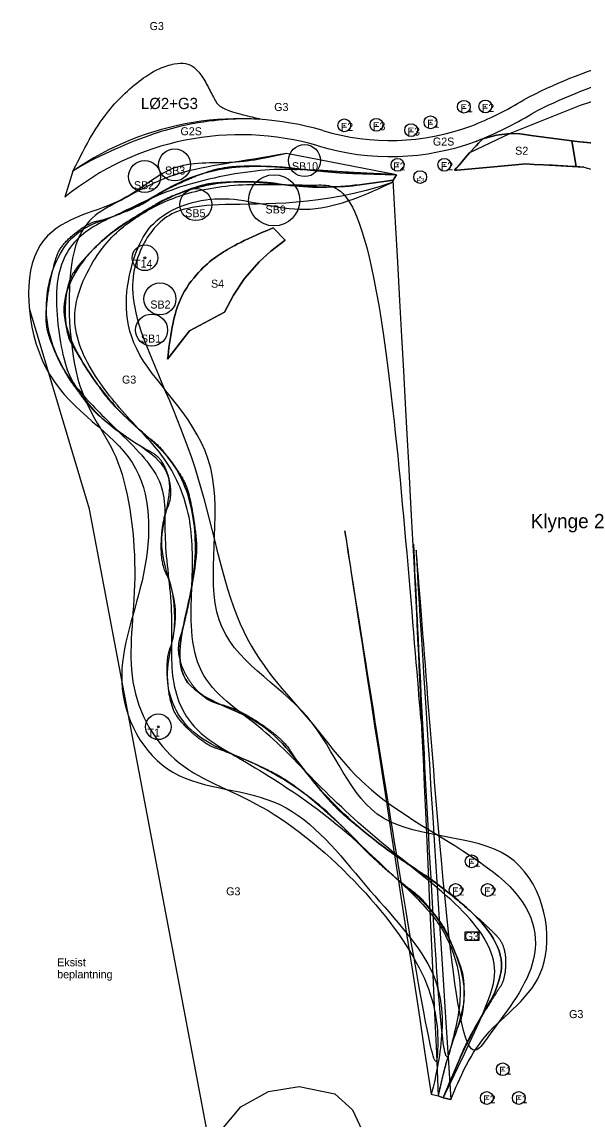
# Model space of a CAD drawing. Extents: x 0 to 512122, y 0 to 6212554.
# Drawn here: x 511416.7 to 511504.4, y 6211506.3 to 6211677.6 of the extents above; entities that cross this region are included whole.
import ezdxf

# ---------------------------------------------------------------- set-up
doc = ezdxf.new("R2010")
doc.units = 0
for name, color, linetype in [('_color plan_G3', 7, 'Continuous'), ('_LØ2', 7, 'Continuous'), ('_ny fruit trees', 7, 'Continuous'), ('_ny grøft', 7, 'Continuous'), ('_Paths', 7, 'Continuous'), ('_S1_rabarber', 7, 'Continuous'), ('_S2_skovjorbær', 7, 'Continuous'), ('_S4_Løvstikke', 7, 'Continuous'), ('L40 jord udlagt muld og grøft', 7, 'Continuous'), ('MatrikelnummerMaster', 7, 'Continuous'), ('Skel', 7, 'Continuous'), ('TV_U_AFM_Symbl_Gul', 7, 'Continuous'), ('TV_U_LYS_Ledn-ror', 7, 'Continuous'), ('TV_U_LYS_Mastenummer', 7, 'Continuous'), ('TV_U_LYS_Nyx330-Trafiksti-x2', 7, 'Continuous')]:
    doc.layers.add(name, color=color, linetype=linetype)

# ---------------------------------------------------------------- blocks, each defined once
blk = doc.blocks.new('SOLITAIRE TREES')
at = {"layer": 'Skel'}
for radius in [2, 0.141]:
    blk.add_circle((0, 0), radius, dxfattribs=at)

msp = doc.modelspace()

# ---------------------------------------------------------------- linework, layer by layer
at = {"layer": '_color plan_G3'}
for p, q in [((511427.31, 6211601.52), (511417.91, 6211632.84)), ((511446.41, 6211500.58), (511427.31, 6211601.52))]:
    msp.add_line(p, q, dxfattribs=at)
at = {"layer": '_LØ2'}
msp.add_open_spline([(511424.7, 6211654.29), (511428.07, 6211656.43), (511437.64, 6211660.56), (511445.41, 6211662.15), (511451.17, 6211662.51), (511454.35, 6211662.34), (511453.5, 6211662.56), (511449.68, 6211663.42), (511447.75, 6211664.26), (511447.04, 6211665.01), (511446.02, 6211667.09), (511444.88, 6211669.21), (511443.53, 6211670.64), (511442.41, 6211671.16), (511440.65, 6211671.16), (511438.15, 6211670.34), (511435.89, 6211669.05), (511432.77, 6211666.48), (511430.26, 6211663.8), (511427.67, 6211660.13), (511424.7, 6211654.29), (511424.7, 6211654.29), (511424.7, 6211654.29)], degree=3, dxfattribs=at)
at = {"layer": '_ny fruit trees'}
for centre, radius in [((511485.78, 6211664.33), 1), ((511489.13, 6211664.38), 1), ((511485.78, 6211664.33), 0.0426), ((511489.13, 6211664.38), 0.0426), ((511467.09, 6211661.42), 1), ((511472.12, 6211661.51), 1), ((511480.57, 6211661.9), 1), ((511480.57, 6211661.9), 0.0426), ((511467.09, 6211661.42), 0.0426), ((511472.12, 6211661.51), 0.0426), ((511477.54, 6211660.68), 1), ((511477.54, 6211660.68), 0.0426), ((511475.42, 6211655.26), 1), ((511475.42, 6211655.26), 0.0426), ((511482.72, 6211655.27), 1), ((511482.72, 6211655.27), 0.0426), ((511478.95, 6211653.35), 1), ((511478.95, 6211653.35), 0.0426), ((511486.99, 6211546.53), 1), ((511486.99, 6211546.53), 0.0426), ((511484.49, 6211542.06), 1), ((511484.49, 6211542.06), 0.0426), ((511489.49, 6211542.06), 1), ((511489.49, 6211542.06), 0.0426), ((511491.86, 6211514.07), 1), ((511491.86, 6211514.07), 0.0426), ((511489.36, 6211509.59), 1), ((511489.36, 6211509.59), 0.0426), ((511494.36, 6211509.59), 1), ((511494.36, 6211509.59), 0.0426)]:
    msp.add_circle(centre, radius, dxfattribs=at)
at = {"layer": '_ny grøft'}
for p, q in [((511474.76, 6211652.85), (511475.27, 6211653.72)), ((511481.79, 6211509.92), (511482.56, 6211509.63))]:
    msp.add_line(p, q, dxfattribs=at)
for points in [[(511475.27, 6211653.72), (511461.62, 6211654.47), (511455.63, 6211655.03), (511441.12, 6211652.28), (511432.39, 6211647.75), (511425.04, 6211644.58), (511421.2, 6211637.22), (511423.26, 6211623.35), (511425.38, 6211620.08), (511431.34, 6211614.04), (511439.77, 6211606.02), (511438.57, 6211597.36), (511440.58, 6211585.48), (511439.53, 6211574.34), (511443.41, 6211566.53), (511450.84, 6211562.71), (511464.22, 6211554.28), (511474.17, 6211544.78), (511480.99, 6211538.55), (511484.19, 6211532.91), (511485.83, 6211525.83), (511483.67, 6211517.14), (511481.79, 6211509.92), (511475.27, 6211653.72), (511481.79, 6211509.92)], [(511482.56, 6211509.63), (511489.4, 6211523.73), (511492.28, 6211529.95), (511486.36, 6211539.12), (511472.41, 6211549.47), (511461.9, 6211559.42), (511454.45, 6211567.71), (511442.74, 6211574.97), (511443.32, 6211589.8), (511443.59, 6211599.75), (511439.99, 6211609.06), (511433.64, 6211615.22), (511427.09, 6211623.08), (511423.49, 6211632.32), (511429.32, 6211643.41), (511435.09, 6211647.54), (511441.15, 6211650.76), (511450.85, 6211652.59), (511462.71, 6211651.81), (511474.76, 6211652.85), (511482.56, 6211509.63), (511474.76, 6211652.85)]]:
    msp.add_open_spline(points, degree=3, dxfattribs=at)
at = {"layer": '_Paths'}
msp.add_line((511424.7, 6211654.29), (511423.42, 6211650.2), dxfattribs=at)
msp.add_lwpolyline([(511487.79, 6211658.98), (511487.77, 6211658.97), (511487.75, 6211658.97)], dxfattribs=at)
for centre, radius, start, end in [((511530.83, 6211597.57), 76.66, 105.9873, 117.7388), ((511530.83, 6211597.57), 74.16, 105.9889, 117.6767), ((511468, 6211709.71), 51.95, 291.3096, 301.5015), ((511450.83, 6211616.67), 45.8, 73.6335, 124.7812), ((511468, 6211709.71), 54.45, 291.3096, 301.4133), ((511474.27, 6211695.48), 36.42, 253.1824, 290.2638), ((511450.83, 6211616.67), 43.3, 73.6461, 129.2584), ((511474.27, 6211695.48), 38.92, 253.1974, 290.2638)]:
    msp.add_arc(centre, radius, start, end, dxfattribs=at)
at = {"layer": '_S1_rabarber'}
for points in [[(511503.34, 6211654.98), (511502.63, 6211659), (511503.91, 6211658.84), (511512.53, 6211658.04)], [(511513.47, 6211657.95), (511503.91, 6211658.84), (511502.63, 6211659), (511503.34, 6211654.98), (511504.51, 6211654.89)], [(511504.51, 6211654.89), (511503.34, 6211654.98)]]:
    msp.add_lwpolyline(points, dxfattribs=at)
at = {"layer": '_S2_skovjorbær'}
msp.add_lwpolyline([(511503.34, 6211654.98), (511502.63, 6211659), (511496.67, 6211659.79), (511495.32, 6211659.98), (511494.51, 6211660.09), (511493.04, 6211660.13), (511490.89, 6211659.92), (511488.72, 6211659.33), (511488.05, 6211658.62), (511487.71, 6211658.25), (511486.68, 6211657.15), (511485.97, 6211656.37), (511485.5, 6211655.78), (511485.29, 6211655.54), (511485.04, 6211655.22), (511484.65, 6211654.8), (511484.32, 6211654.41), (511484.32, 6211654.41), (511484.32, 6211654.41), (511484.74, 6211654.44), (511489.91, 6211654.92), (511492.7, 6211655.16), (511495.49, 6211655.44), (511496.78, 6211655.34), (511499.65, 6211655.23), (511502.01, 6211655.06), (511503.34, 6211654.98)], dxfattribs=at)
msp.add_lwpolyline([(511502.01, 6211655.06), (511499.65, 6211655.23), (511496.78, 6211655.34), (511495.49, 6211655.44), (511492.7, 6211655.16), (511489.91, 6211654.92), (511484.74, 6211654.44), (511484.32, 6211654.41), (511484.65, 6211654.8), (511485.04, 6211655.22), (511485.29, 6211655.54), (511485.5, 6211655.78), (511485.97, 6211656.37), (511486.68, 6211657.15), (511487.71, 6211658.25), (511488.05, 6211658.62), (511488.72, 6211659.33), (511490.89, 6211659.92), (511493.04, 6211660.13), (511494.51, 6211660.09), (511496.67, 6211659.79), (511502.63, 6211659), (511503.34, 6211654.98)], close=True, dxfattribs=at)
at = {"layer": '_S4_Løvstikke'}
for points in [[(511439.49, 6211624.95), (511442.9, 6211629.35), (511448.4, 6211632.28), (511449.8, 6211634.9), (511451.53, 6211637.52), (511453.79, 6211640.12), (511455.62, 6211641.78), (511457.84, 6211643.49), (511455.99, 6211645.42)], [(511455.99, 6211645.42), (511457.84, 6211643.49), (511455.62, 6211641.78), (511453.79, 6211640.12), (511451.53, 6211637.52), (511449.8, 6211634.9), (511448.4, 6211632.28), (511442.9, 6211629.35), (511439.49, 6211624.95)]]:
    msp.add_lwpolyline(points, dxfattribs=at)
for points in [[(511455.99, 6211645.42), (511450.89, 6211643.32), (511447.17, 6211641.07), (511444.84, 6211639.2), (511441.51, 6211635.17), (511440.06, 6211629.91), (511439.66, 6211626.47), (511439.49, 6211624.95)], [(511439.49, 6211624.95), (511439.66, 6211626.47), (511440.06, 6211629.91), (511441.51, 6211635.17), (511444.84, 6211639.2), (511447.17, 6211641.07), (511450.89, 6211643.32), (511455.99, 6211645.42)]]:
    msp.add_open_spline(points, degree=3, dxfattribs=at)
at = {"layer": 'L40 jord udlagt muld og grøft'}
for p, q in [((511475.27, 6211653.72), (511458.09, 6211657.05)), ((511475.27, 6211653.72), (511458.09, 6211657.05)), ((511475.27, 6211653.72), (511474.76, 6211652.85)), ((511474.76, 6211652.85), (511474.56, 6211652.51)), ((511474.56, 6211652.51), (511474.76, 6211652.85)), ((511480.69, 6211510.17), (511481.79, 6211509.92)), ((511480.69, 6211510.17), (511481.79, 6211509.92)), ((511482.56, 6211509.63), (511481.79, 6211509.92)), ((511483.74, 6211509.33), (511482.56, 6211509.63)), ((511482.56, 6211509.63), (511483.74, 6211509.33))]:
    msp.add_line(p, q, dxfattribs=at)
msp.add_lwpolyline([(511485.92, 6211535.46), (511485.92, 6211534.21), (511488.18, 6211534.21), (511488.18, 6211535.46)], close=True, dxfattribs=at)
for points, degree in [([(511458.09, 6211657.05), (511455.68, 6211656.49), (511449.86, 6211655.14), (511439.81, 6211656.13), (511432.57, 6211648.34), (511415.88, 6211645.78), (511418.42, 6211619.6), (511437.09, 6211610.57), (511436.92, 6211590.82), (511429.65, 6211574.72), (511438.49, 6211557.45), (511458.39, 6211558.11), (511470.26, 6211542.38), (511482.66, 6211529.65), (511482.5, 6211517.37), (511481.15, 6211511.98), (511480.69, 6211510.17)], 3), ([(511458.09, 6211657.05), (511450.76, 6211655.72), (511440.25, 6211654.54), (511431.71, 6211649.18), (511423.32, 6211645.64), (511424.22, 6211618.55), (511432.73, 6211611.07), (511435.28, 6211589.93), (511432.23, 6211574.25), (511440.19, 6211560.26), (511454.86, 6211556.18), (511471.47, 6211541.66), (511481.58, 6211526.77), (511481.91, 6211515.67), (511480.69, 6211510.17), (511458.09, 6211657.05), (511480.69, 6211510.17)], 3), ([(511481.79, 6211509.92), (511482.35, 6211512.33), (511483.58, 6211517.63), (511486.76, 6211525.23), (511484.49, 6211532.79), (511480.87, 6211539.63), (511472.71, 6211545.48), (511464.18, 6211555.25), (511453.41, 6211562.14), (511442.62, 6211565.61), (511437.96, 6211575.2), (511442.41, 6211585.85), (511436.7, 6211596.01), (511442.33, 6211607.71), (511431.47, 6211613.15), (511426.2, 6211618.74), (511421.25, 6211626.12), (511419.76, 6211635.3), (511424.12, 6211645.62), (511433.33, 6211647.42), (511442.15, 6211653.77), (511452.77, 6211655.6), (511464.14, 6211654.06), (511470.71, 6211653.86), (511475.27, 6211653.72)], 3), ([(511481.79, 6211509.92), (511482.35, 6211512.33), (511483.58, 6211517.63), (511486.76, 6211525.23), (511484.49, 6211532.79), (511480.87, 6211539.63), (511472.71, 6211545.48), (511464.18, 6211555.25), (511453.41, 6211562.14), (511442.62, 6211565.61), (511437.96, 6211575.2), (511442.41, 6211585.85), (511436.7, 6211596.01), (511442.33, 6211607.71), (511431.47, 6211613.15), (511426.2, 6211618.74), (511421.25, 6211626.12), (511419.76, 6211635.3), (511424.12, 6211645.62), (511433.33, 6211647.42), (511442.15, 6211653.77), (511452.77, 6211655.6), (511464.14, 6211654.06), (511470.71, 6211653.86), (511475.27, 6211653.72)], 3), ([(511441.12, 6211652.28), (511445.57, 6211654.36), (511450.69, 6211655.24), (511455.63, 6211655.03)], 2), ([(511455.63, 6211655.03), (511457.65, 6211654.94), (511459.63, 6211654.67), (511461.62, 6211654.47)], 2), ([(511461.62, 6211654.47), (511466.15, 6211654), (511470.71, 6211653.86), (511475.27, 6211653.72)], 2), ([(511482.56, 6211509.63), (511484.52, 6211514.31), (511487.33, 6211521.04), (511494.46, 6211531.2), (511484.43, 6211541.62), (511473.09, 6211548.33), (511462.09, 6211558.19), (511455.18, 6211569.44), (511438.69, 6211572.97), (511443.7, 6211588.59), (511444.23, 6211599.66), (511440.98, 6211609.39), (511432.98, 6211615.29), (511426.97, 6211622.66), (511421.35, 6211633.12), (511427.65, 6211642.85), (511434.98, 6211647.51), (511441.89, 6211651.59), (511451.56, 6211653.25), (511462.77, 6211651.15), (511470.74, 6211652.28), (511474.76, 6211652.85)], 3), ([(511474.76, 6211652.85), (511470.74, 6211652.28), (511462.77, 6211651.15), (511451.56, 6211653.25), (511441.89, 6211651.59), (511434.98, 6211647.51), (511427.65, 6211642.85), (511421.35, 6211633.12), (511426.97, 6211622.66), (511432.98, 6211615.29), (511440.98, 6211609.39), (511444.23, 6211599.66), (511443.7, 6211588.59), (511438.69, 6211572.97), (511455.18, 6211569.44), (511462.09, 6211558.19), (511473.09, 6211548.33), (511484.43, 6211541.62), (511494.46, 6211531.2), (511487.33, 6211521.04), (511484.52, 6211514.31), (511482.56, 6211509.63)], 3), ([(511483.74, 6211509.33), (511485.11, 6211512.64), (511488.42, 6211520.65), (511501.36, 6211528.2), (511496.23, 6211551.58), (511469.85, 6211549.2), (511463.78, 6211571.11), (511442.68, 6211581.04), (511450.76, 6211610.16), (511431.68, 6211625.71), (511433.47, 6211640.43), (511437.47, 6211647.98), (511448.92, 6211651.3), (511461.52, 6211646.46), (511470.94, 6211650.83), (511474.56, 6211652.51)], 3), ([(511432.39, 6211647.75), (511435.49, 6211648.98), (511438.16, 6211650.89), (511441.12, 6211652.28)], 2), ([(511474.56, 6211652.51), (511463.59, 6211648.7), (511444.99, 6211649.71), (511438.23, 6211647.27), (511434.17, 6211640.84), (511433.22, 6211631.63), (511444.92, 6211608.82), (511449.42, 6211581.02), (511462.31, 6211568.82), (511470.45, 6211556.04), (511495.94, 6211543.51), (511498.54, 6211530.24), (511488.73, 6211518.74), (511483.74, 6211509.33), (511474.56, 6211652.51), (511483.74, 6211509.33)], 3), ([(511450.85, 6211652.59), (511447.54, 6211652.56), (511444.21, 6211651.99), (511441.15, 6211650.76)], 2), ([(511462.71, 6211651.81), (511458.77, 6211651.9), (511454.83, 6211652.64), (511450.85, 6211652.59)], 2), ([(511474.76, 6211652.85), (511470.74, 6211652.28), (511466.72, 6211651.71), (511462.71, 6211651.81)], 2), ([(511441.15, 6211650.76), (511439.03, 6211649.9), (511437.04, 6211648.73), (511435.09, 6211647.54)], 2), ([(511425.04, 6211644.58), (511427.04, 6211646.19), (511429.86, 6211646.74), (511432.39, 6211647.75)], 2), ([(511435.09, 6211647.54), (511433.08, 6211646.31), (511431.12, 6211645.06), (511429.32, 6211643.41)], 2), ([(511421.2, 6211637.22), (511421.78, 6211640.07), (511422.97, 6211642.9), (511425.04, 6211644.58)], 2), ([(511429.32, 6211643.41), (511426.14, 6211640.51), (511423.47, 6211636.39), (511423.49, 6211632.32)], 2), ([(511423.26, 6211623.35), (511421.03, 6211627.48), (511420.23, 6211632.39), (511421.2, 6211637.22)], 2), ([(511423.49, 6211632.32), (511423.51, 6211629.11), (511425.21, 6211625.94), (511427.09, 6211623.08)], 2), ([(511425.38, 6211620.08), (511424.61, 6211621.12), (511423.88, 6211622.2), (511423.26, 6211623.35)], 2), ([(511427.09, 6211623.08), (511429.03, 6211620.14), (511431.15, 6211617.54), (511433.64, 6211615.22)], 2), ([(511431.34, 6211614.04), (511428.91, 6211615.86), (511427.05, 6211617.84), (511425.38, 6211620.08)], 2), ([(511439.77, 6211606.02), (511439.04, 6211609.36), (511434.66, 6211611.55), (511431.34, 6211614.04)], 2), ([(511433.64, 6211615.22), (511435.79, 6211613.21), (511438.23, 6211611.41), (511439.99, 6211609.06)], 2), ([(511439.99, 6211609.06), (511441.98, 6211606.4), (511443.11, 6211603.02), (511443.59, 6211599.75)], 2), ([(511438.57, 6211597.36), (511438.8, 6211600.36), (511440.31, 6211603.51), (511439.77, 6211606.02)], 2), ([(511443.59, 6211599.75), (511444.08, 6211596.48), (511443.93, 6211593.32), (511443.32, 6211589.8)], 2), ([(511440.58, 6211585.48), (511440.41, 6211589.41), (511438.26, 6211593.23), (511438.57, 6211597.36)], 2), ([(511443.32, 6211589.8), (511442.41, 6211584.56), (511440.48, 6211578.55), (511442.74, 6211574.97)], 2), ([(511439.53, 6211574.34), (511439.17, 6211578.11), (511440.73, 6211581.84), (511440.58, 6211585.48)], 2), ([(511442.74, 6211574.97), (511444.84, 6211571.65), (511450.56, 6211570.43), (511454.45, 6211567.71)], 2), ([(511443.41, 6211566.53), (511441.25, 6211568.45), (511439.81, 6211571.4), (511439.53, 6211574.34)], 2), ([(511454.45, 6211567.71), (511457.6, 6211565.51), (511459.55, 6211562.33), (511461.9, 6211559.42)], 2), ([(511450.84, 6211562.71), (511448.22, 6211563.81), (511445.48, 6211564.69), (511443.41, 6211566.53)], 2), ([(511464.22, 6211554.28), (511460.27, 6211557.75), (511455.78, 6211560.62), (511450.84, 6211562.71)], 2), ([(511461.9, 6211559.42), (511464.94, 6211555.64), (511468.65, 6211552.32), (511472.41, 6211549.47)], 2), ([(511474.17, 6211544.78), (511470.68, 6211547.8), (511467.65, 6211551.26), (511464.22, 6211554.28)], 2), ([(511472.41, 6211549.47), (511476.93, 6211546.06), (511481.53, 6211543.33), (511486.36, 6211539.12)], 2), ([(511480.99, 6211538.55), (511479.08, 6211540.92), (511476.52, 6211542.75), (511474.17, 6211544.78)], 2), ([(511484.19, 6211532.91), (511483.35, 6211534.95), (511482.33, 6211536.88), (511480.99, 6211538.55)], 2), ([(511486.36, 6211539.12), (511489.39, 6211536.47), (511492.5, 6211533.24), (511492.28, 6211529.95)], 2), ([(511485.83, 6211525.83), (511485.87, 6211528.21), (511485.14, 6211530.63), (511484.19, 6211532.91)], 2), ([(511492.28, 6211529.95), (511492.14, 6211527.89), (511490.67, 6211525.81), (511489.4, 6211523.73)], 2), ([(511483.67, 6211517.14), (511484.58, 6211520.03), (511485.79, 6211522.9), (511485.83, 6211525.83)], 2), ([(511489.4, 6211523.73), (511486.47, 6211518.99), (511484.52, 6211514.31), (511482.56, 6211509.63)], 2), ([(511481.79, 6211509.92), (511482.35, 6211512.33), (511482.91, 6211514.74), (511483.67, 6211517.14)], 2)]:
    msp.add_open_spline(points, degree=degree, dxfattribs=at)
at = {"layer": 'MatrikelnummerMaster'}
msp.add_lwpolyline([(511553.97, 6211656.1), (511555.79, 6211657.96), (511557.93, 6211663.87), (511551.03, 6211666.35), (511543, 6211668.4), (511536.48, 6211669.29), (511529.07, 6211669.77), (511518.64, 6211668.43), (511511.1, 6211666.82), (511503.97, 6211664.54), (511497.17, 6211661.84), (511493.04, 6211660.13), (511486.68, 6211657.15), (511484.32, 6211654.41), (511495.49, 6211655.44), (511504.51, 6211654.89), (511516.18, 6211651.73), (511523.38, 6211648.45), (511530.14, 6211644.26), (511535.92, 6211638.78)], close=True, dxfattribs=at)
at = {"layer": 'TV_U_LYS_Mastenummer'}
for centre, radius in [((511460.89, 6211655.92), 2.5), ((511460.89, 6211655.92), 2.5), ((511440.59, 6211655.25), 2.5), ((511440.59, 6211655.25), 2.5), ((511435.9, 6211653.43), 2.5), ((511435.9, 6211653.43), 2.5), ((511456.13, 6211649.72), 4), ((511456.13, 6211649.72), 4), ((511443.91, 6211649.05), 2.5), ((511443.91, 6211649.05), 2.5), ((511438.3, 6211634.33), 2.5), ((511438.3, 6211634.33), 2.5), ((511436.99, 6211629.47), 2.5), ((511436.99, 6211629.47), 2.5)]:
    msp.add_circle(centre, radius, dxfattribs=at)
at = {"layer": 'TV_U_LYS_Nyx330-Trafiksti-x2'}
msp.add_lwpolyline([(511446.07, 6211502.4), (511450.93, 6211508.22), (511455.27, 6211510.57), (511460.06, 6211511.36), (511465.63, 6211510.21), (511468.37, 6211507.75), (511470.56, 6211503.03)], dxfattribs=at)

# ---------------------------------------------------------------- block references
at = {"layer": 'Skel'}
for p in [(511435.94, 6211640.75), (511438.04, 6211567.53)]:
    msp.add_blockref('SOLITAIRE TREES', p, dxfattribs=at)

# ---------------------------------------------------------------- texts
at = {"layer": 'TV_U_AFM_Symbl_Gul'}
for s, height, p in [('G3', 1.25, (511436.68, 6211676.3)), ('LØ2+G3', 1.75, (511435.32, 6211663.97)), ('G3', 1.25, (511456.15, 6211663.67)), ('F1', 1.25, (511485.23, 6211663.48)), ('F2', 1.25, (511488.58, 6211663.53)), ('F2', 1.25, (511466.54, 6211660.57)), ('F3', 1.25, (511471.57, 6211660.66)), ('F1', 1.25, (511480.02, 6211661.05)), ('G2S', 1.25, (511441.5, 6211659.88)), ('F3', 1.25, (511476.98, 6211659.84)), ('G2S', 1.25, (511480.94, 6211658.27)), ('S2', 1.25, (511493.8, 6211656.84)), ('SB3', 1.25, (511439.08, 6211653.75)), ('SB10', 1.25, (511458.91, 6211654.42)), ('F2', 1.25, (511474.73, 6211654.38)), ('F2', 1.25, (511482.16, 6211654.43)), ('F3', 0.725, (511478.4, 6211652.5)), ('SB2', 1.25, (511434.23, 6211651.46)), ('SB5', 1.25, (511442.24, 6211647.09)), ('SB9', 1.25, (511454.79, 6211647.67)), ('T14', 1.25, (511434.24, 6211639.21)), ('S4', 1.25, (511446.27, 6211636.08)), ('SB2', 1.25, (511436.79, 6211632.83)), ('SB1', 1.25, (511435.32, 6211627.51)), ('G3', 1.25, (511432.36, 6211621.11)), ('T1', 1.25, (511436.34, 6211565.99)), ('F1', 1.25, (511486.43, 6211545.68)), ('G3', 1.25, (511448.64, 6211541.22)), ('F2', 1.25, (511483.93, 6211541.21)), ('F2', 1.25, (511488.93, 6211541.21)), ('G3', 1.25, (511485.92, 6211534.21)), ('Eksist', 1.25, (511422.24, 6211530.14)), ('beplantning', 1.25, (511422.24, 6211528.27)), ('G3', 1.25, (511502.22, 6211522.05)), ('F1', 1.25, (511491.3, 6211513.22)), ('F2', 1.25, (511488.8, 6211508.75)), ('F1', 1.25, (511493.8, 6211508.75))]:
    msp.add_text(s, height=height, dxfattribs=at).set_placement(p)
at = {"layer": 'TV_U_LYS_Ledn-ror'}
msp.add_text('Klynge 2', height=2.219, dxfattribs=at).set_placement((511496.21, 6211598.54))

doc.saveas('drawing.dxf')
